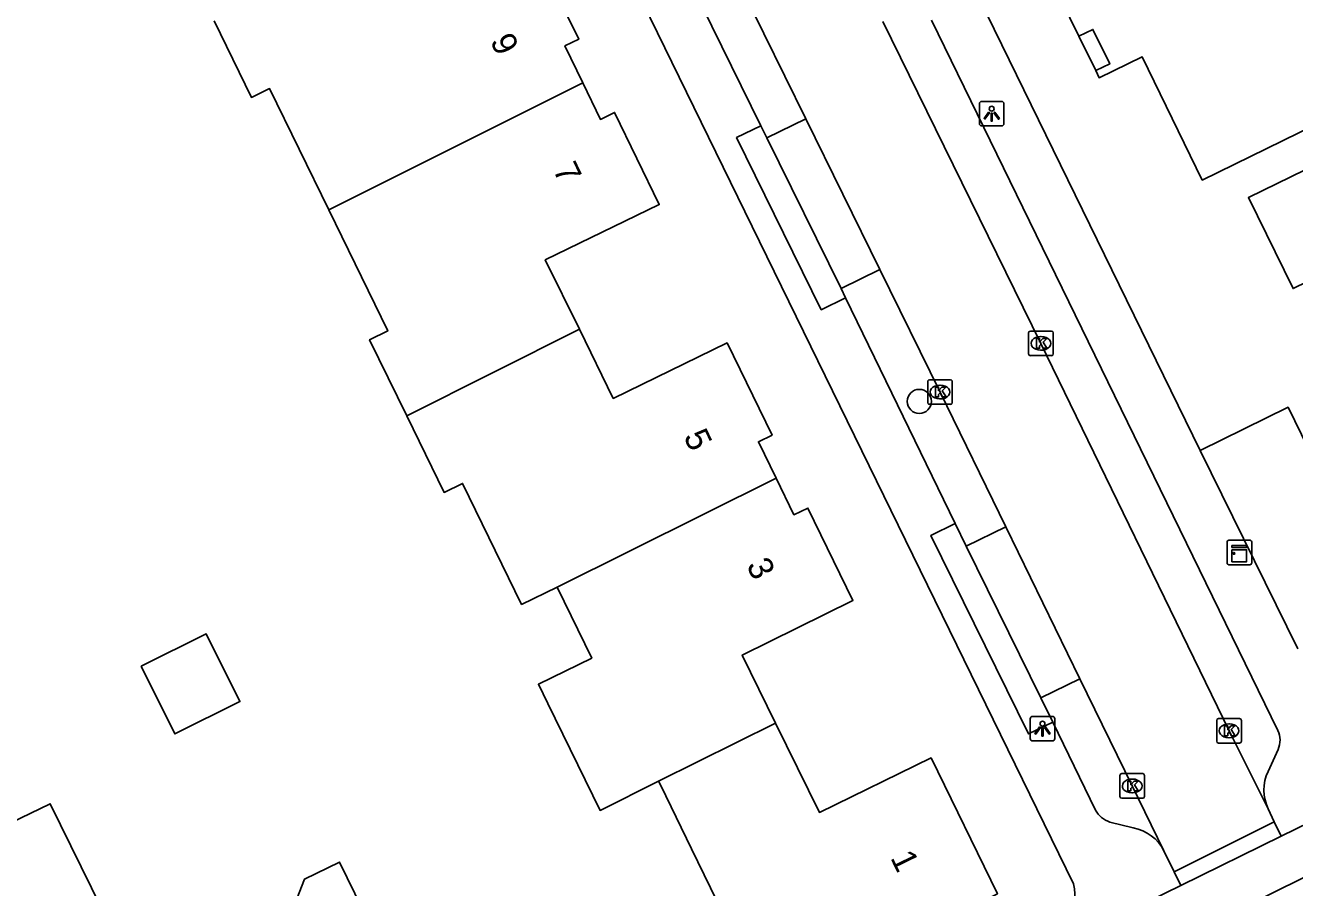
# Model space of a CAD drawing. Extents: x 160457 to 162082, y 388340 to 389736.
# Drawn here: x 160698.8 to 160750.4, y 388835.3 to 388870.3 of the extents above; entities that cross this region are included whole.
import ezdxf

# ---------------------------------------------------------------- set-up
doc = ezdxf.new("R2010")
doc.units = 0
for name, color, linetype in [('IMGEO_Boom', 7, 'Continuous'), ('IMGEO_Fietspad_gesloten', 7, 'Continuous'), ('IMGEO_Kast', 7, 'Continuous'), ('IMGEO_Kolk', 7, 'Continuous'), ('IMGEO_Lichtpunt', 7, 'Continuous'), ('IMGEO_Pand', 7, 'Continuous'), ('IMGEO_Pand_nummerreeks', 7, 'Continuous'), ('IMGEO_Pand_overbouw', 7, 'Continuous'), ('IMGEO_Parkeervlak_open', 7, 'Continuous'), ('IMGEO_Rijbaan_lokaal_gesloten', 7, 'Continuous'), ('IMGEO_Voetpad_open', 7, 'Continuous')]:
    doc.layers.add(name, color=color, linetype=linetype)

msp = doc.modelspace()

# ---------------------------------------------------------------- linework, layer by layer
at = {"layer": 'IMGEO_Boom'}
msp.add_circle((160735.122, 388855.034), 0.489, dxfattribs=at)
at = {"layer": 'IMGEO_Fietspad_gesloten'}
msp.add_lwpolyline([(160688.114, 388804.953), (160696.889, 388809.242), (160739.38, 388830.051), (160752.018, 388836.29), (160804.151, 388861.828), (160812.524, 388865.895)], dxfattribs=at)
at = {"layer": 'IMGEO_Kast'}
for p, q in [((160747.638, 388848.463), (160747.638, 388849.304)), ((160747.638, 388849.304), (160747.638, 388848.463)), ((160747.713, 388849.388), (160748.554, 388849.388)), ((160748.554, 388849.388), (160747.713, 388849.388)), ((160748.638, 388849.313), (160748.638, 388848.472)), ((160748.638, 388848.472), (160748.638, 388849.313)), ((160748.563, 388848.388), (160747.722, 388848.388)), ((160747.722, 388848.388), (160748.563, 388848.388))]:
    msp.add_line(p, q, dxfattribs=at)
for points in [[(160747.833, 388849.178), (160748.433, 388849.178), (160748.433, 388849.093), (160747.833, 388849.093), (160747.833, 388849.178)], [(160747.833, 388849.003), (160748.433, 388849.003), (160748.433, 388848.514), (160747.833, 388848.514), (160747.833, 388849.003)]]:
    msp.add_lwpolyline(points, dxfattribs=at)
msp.add_circle((160747.917, 388848.852), 0.0377, dxfattribs=at)
for centre, start, end in [((160747.716, 388849.31), 92.4484, 184.2845), ((160747.716, 388849.31), 92.4484, 184.2845), ((160748.56, 388849.31), 2.4484, 94.2845), ((160748.56, 388849.31), 2.4484, 94.2845), ((160747.716, 388848.466), 182.4484, 274.2845), ((160747.716, 388848.466), 182.4484, 274.2845), ((160748.56, 388848.466), 272.4484, 4.2845), ((160748.56, 388848.466), 272.4484, 4.2845)]:
    msp.add_arc(centre, 0.0779, start, end, dxfattribs=at)
at = {"layer": 'IMGEO_Kolk'}
for p, q in [((160739.566, 388856.967), (160739.566, 388857.819)), ((160739.641, 388857.893), (160740.493, 388857.893)), ((160740.567, 388857.819), (160740.567, 388856.967)), ((160740.054, 388857.673), (160740.079, 388857.673)), ((160740.493, 388856.893), (160739.641, 388856.893)), ((160740.077, 388857.113), (160740.052, 388857.113)), ((160735.463, 388854.988), (160735.463, 388855.84)), ((160735.538, 388855.914), (160736.39, 388855.914)), ((160736.464, 388855.84), (160736.464, 388854.988)), ((160735.951, 388855.694), (160735.976, 388855.694)), ((160736.39, 388854.914), (160735.538, 388854.914)), ((160735.974, 388855.134), (160735.949, 388855.134)), ((160747.218, 388841.212), (160747.218, 388842.064)), ((160747.293, 388842.138), (160748.145, 388842.138)), ((160747.706, 388841.918), (160747.731, 388841.918)), ((160748.219, 388842.064), (160748.219, 388841.212)), ((160747.729, 388841.358), (160747.704, 388841.358)), ((160748.145, 388841.138), (160747.293, 388841.138)), ((160743.279, 388838.97), (160743.279, 388839.822)), ((160743.354, 388839.896), (160744.206, 388839.896)), ((160744.28, 388839.822), (160744.28, 388838.97)), ((160743.767, 388839.676), (160743.792, 388839.676)), ((160744.206, 388838.896), (160743.354, 388838.896)), ((160743.79, 388839.116), (160743.765, 388839.116))]:
    msp.add_line(p, q, dxfattribs=at)
for points in [[(160739.566, 388856.967), (160739.566, 388857.819)], [(160739.641, 388857.893), (160740.493, 388857.893)], [(160740.567, 388857.819), (160740.567, 388856.967)], [(160739.887, 388857.593), (160740.01, 388857.593), (160740.01, 388857.442), (160740.14, 388857.593), (160740.304, 388857.593), (160740.158, 388857.442), (160740.311, 388857.193), (160740.159, 388857.193), (160740.074, 388857.357), (160740.01, 388857.29), (160740.01, 388857.193), (160739.887, 388857.193), (160739.887, 388857.593)], [(160740.493, 388856.893), (160739.641, 388856.893)], [(160735.463, 388854.988), (160735.463, 388855.84)], [(160735.538, 388855.914), (160736.39, 388855.914)], [(160736.464, 388855.84), (160736.464, 388854.988)], [(160735.784, 388855.614), (160735.907, 388855.614), (160735.907, 388855.463), (160736.037, 388855.614), (160736.201, 388855.614), (160736.055, 388855.463), (160736.208, 388855.214), (160736.056, 388855.214), (160735.971, 388855.378), (160735.907, 388855.311), (160735.907, 388855.214), (160735.784, 388855.214), (160735.784, 388855.614)], [(160736.39, 388854.914), (160735.538, 388854.914)], [(160747.218, 388841.212), (160747.218, 388842.064)], [(160747.293, 388842.138), (160748.145, 388842.138)], [(160747.539, 388841.838), (160747.662, 388841.838), (160747.662, 388841.687), (160747.792, 388841.838), (160747.956, 388841.838), (160747.81, 388841.687), (160747.963, 388841.438), (160747.811, 388841.438), (160747.726, 388841.602), (160747.662, 388841.535), (160747.662, 388841.438), (160747.539, 388841.438), (160747.539, 388841.838)], [(160748.219, 388842.064), (160748.219, 388841.212)], [(160748.145, 388841.138), (160747.293, 388841.138)], [(160743.279, 388838.97), (160743.279, 388839.822)], [(160743.354, 388839.896), (160744.206, 388839.896)], [(160744.28, 388839.822), (160744.28, 388838.97)], [(160743.6, 388839.596), (160743.723, 388839.596), (160743.723, 388839.445), (160743.853, 388839.596), (160744.017, 388839.596), (160743.871, 388839.445), (160744.024, 388839.196), (160743.872, 388839.196), (160743.787, 388839.36), (160743.723, 388839.293), (160743.723, 388839.196), (160743.6, 388839.196), (160743.6, 388839.596)], [(160744.206, 388838.896), (160743.354, 388838.896)]]:
    msp.add_lwpolyline(points, dxfattribs=at)
for centre, start, end in [((160739.643, 388857.817), 91.552, 178.448), ((160739.643, 388857.817), 91.552, 178.448), ((160740.491, 388857.817), 1.552, 88.448), ((160740.491, 388857.817), 1.552, 88.448), ((160739.643, 388856.969), 181.552, 268.448), ((160739.643, 388856.969), 181.552, 268.448), ((160740.491, 388856.969), 271.552, 358.448), ((160740.491, 388856.969), 271.552, 358.448), ((160735.54, 388855.838), 91.552, 178.448), ((160735.54, 388855.838), 91.552, 178.448), ((160736.388, 388855.838), 1.552, 88.448), ((160736.388, 388855.838), 1.552, 88.448), ((160735.54, 388854.99), 181.552, 268.448), ((160735.54, 388854.99), 181.552, 268.448), ((160736.388, 388854.99), 271.552, 358.448), ((160736.388, 388854.99), 271.552, 358.448), ((160747.295, 388842.062), 91.552, 178.448), ((160747.295, 388842.062), 91.552, 178.448), ((160748.143, 388842.062), 1.552, 88.448), ((160748.143, 388842.062), 1.552, 88.448), ((160747.295, 388841.214), 181.552, 268.448), ((160747.295, 388841.214), 181.552, 268.448), ((160748.143, 388841.214), 271.552, 358.448), ((160748.143, 388841.214), 271.552, 358.448), ((160743.356, 388839.82), 91.552, 178.448), ((160743.356, 388839.82), 91.552, 178.448), ((160744.204, 388839.82), 1.552, 88.448), ((160744.204, 388839.82), 1.552, 88.448), ((160743.356, 388838.972), 181.552, 268.448), ((160743.356, 388838.972), 181.552, 268.448), ((160744.204, 388838.972), 271.552, 358.448), ((160744.204, 388838.972), 271.552, 358.448)]:
    msp.add_arc(centre, 0.0765, start, end, dxfattribs=at)
for centre, major_axis, ratio, start_param, end_param in [((160740.053, 388857.393), (-0.387, 0.002), 0.722429, 4.712389, 7.853982), ((160740.078, 388857.393), (-0.39, 0.002), 0.717154, 1.570796, 4.712389), ((160735.95, 388855.414), (-0.387, 0.002), 0.722429, 4.712389, 7.853982), ((160735.975, 388855.414), (-0.39, 0.002), 0.717154, 1.570796, 4.712389), ((160747.705, 388841.638), (-0.387, 0.002), 0.722429, 4.712389, 7.853982), ((160747.73, 388841.638), (-0.39, 0.002), 0.717154, 1.570796, 4.712389), ((160743.766, 388839.396), (-0.387, 0.002), 0.722429, 4.712389, 7.853982), ((160743.791, 388839.396), (-0.39, 0.002), 0.717154, 1.570796, 4.712389)]:
    msp.add_ellipse(centre, major_axis=major_axis, ratio=ratio, start_param=start_param, end_param=end_param, dxfattribs=at)
at = {"layer": 'IMGEO_Lichtpunt'}
for p, q in [((160737.566, 388867.136), (160737.566, 388866.329)), ((160737.566, 388867.136), (160737.566, 388866.329)), ((160738.468, 388867.231), (160737.66, 388867.231)), ((160738.468, 388867.231), (160737.66, 388867.231)), ((160738.562, 388866.329), (160738.562, 388867.136)), ((160738.562, 388866.329), (160738.562, 388867.136)), ((160737.66, 388866.235), (160738.468, 388866.235)), ((160737.66, 388866.235), (160738.468, 388866.235)), ((160739.632, 388842.131), (160739.632, 388841.324)), ((160739.632, 388842.131), (160739.632, 388841.324)), ((160740.534, 388842.226), (160739.726, 388842.226)), ((160740.534, 388842.226), (160739.726, 388842.226)), ((160740.628, 388841.324), (160740.628, 388842.131)), ((160740.628, 388841.324), (160740.628, 388842.131)), ((160739.726, 388841.23), (160740.534, 388841.23)), ((160739.726, 388841.23), (160740.534, 388841.23))]:
    msp.add_line(p, q, dxfattribs=at)
for points in [[(160737.94, 388866.8), (160737.979, 388866.772), (160737.791, 388866.51), (160737.753, 388866.537), (160737.94, 388866.8)], [(160738.042, 388866.752), (160738.089, 388866.752), (160738.089, 388866.43), (160738.042, 388866.43), (160738.042, 388866.752)], [(160738.152, 388866.772), (160738.19, 388866.799), (160738.377, 388866.537), (160738.338, 388866.509), (160738.152, 388866.772)], [(160740.006, 388841.795), (160740.045, 388841.767), (160739.857, 388841.505), (160739.819, 388841.532), (160740.006, 388841.795)], [(160740.108, 388841.747), (160740.155, 388841.747), (160740.155, 388841.425), (160740.108, 388841.425), (160740.108, 388841.747)], [(160740.218, 388841.767), (160740.256, 388841.794), (160740.443, 388841.532), (160740.404, 388841.504), (160740.218, 388841.767)]]:
    msp.add_lwpolyline(points, dxfattribs=at)
for centre in [(160738.065, 388866.934), (160740.131, 388841.929)]:
    msp.add_circle(centre, 0.0994, dxfattribs=at)
for centre, start, end in [((160737.66, 388867.136), 90, 180), ((160737.66, 388867.136), 90, 180), ((160738.468, 388867.136), 0, 90), ((160738.468, 388867.136), 0, 90), ((160737.66, 388866.329), 180, 270), ((160737.66, 388866.329), 180, 270), ((160738.468, 388866.329), 270, 0), ((160738.468, 388866.329), 270, 360), ((160739.726, 388842.131), 90, 180), ((160739.726, 388842.131), 90, 180), ((160740.534, 388842.131), 0, 90), ((160740.534, 388842.131), 0, 90), ((160739.726, 388841.324), 180, 270), ((160739.726, 388841.324), 180, 270), ((160740.534, 388841.324), 270, 0), ((160740.534, 388841.324), 270, 360)]:
    msp.add_arc(centre, 0.0946, start, end, dxfattribs=at)
at = {"layer": 'IMGEO_Pand'}
for points in [[(160743.031, 388878.682), (160744.402, 388875.881), (160739.785, 388873.622), (160741.614, 388869.885), (160742.18, 388870.162), (160742.864, 388868.756), (160742.295, 388868.485), (160742.434, 388868.193), (160744.178, 388869.046), (160746.63, 388864.032), (160755.794, 388868.515), (160753.342, 388873.528), (160751.802, 388876.678), (160752.565, 388877.051), (160750.081, 388882.13)], [(160713.447, 388874.052), (160714.817, 388871.237), (160719.445, 388873.496), (160721.27, 388869.757), (160720.713, 388869.485), (160721.437, 388867.984)], [(160711.105, 388862.816), (160708.698, 388867.75), (160707.963, 388867.392), (160706.442, 388870.511)], [(160711.105, 388862.816), (160721.437, 388867.984)], [(160721.437, 388867.984), (160722.153, 388866.501), (160722.732, 388866.781), (160724.548, 388863.034), (160719.913, 388860.788), (160721.297, 388857.969)], [(160750.812, 388864.45), (160748.507, 388863.323), (160750.319, 388859.62), (160752.624, 388860.747)], [(160714.281, 388854.442), (160712.77, 388857.539), (160713.504, 388857.897), (160711.105, 388862.816)], [(160721.297, 388857.969), (160714.281, 388854.442)], [(160721.297, 388857.969), (160722.678, 388855.155), (160727.307, 388857.413), (160729.136, 388853.664), (160728.578, 388853.393), (160729.299, 388851.912)], [(160755.566, 388854.723), (160751.768, 388851.437), (160750.115, 388854.798), (160746.543, 388853.042)], [(160720.392, 388847.485), (160718.95, 388846.781), (160716.551, 388851.699), (160715.798, 388851.332), (160714.281, 388854.442)], [(160750.513, 388844.965), (160746.543, 388853.042)], [(160720.392, 388847.485), (160729.299, 388851.912)], [(160729.299, 388851.912), (160730.023, 388850.423), (160730.593, 388850.692), (160732.422, 388846.942), (160727.922, 388844.718), (160729.279, 388841.953)], [(160724.522, 388839.587), (160722.139, 388838.402), (160720.022, 388842.743), (160719.636, 388843.534), (160721.803, 388844.592), (160720.392, 388847.485)], [(160703.475, 388844.266), (160706.119, 388845.585), (160707.494, 388842.828), (160704.85, 388841.509), (160703.475, 388844.266)], [(160729.279, 388841.953), (160731.062, 388838.319), (160735.599, 388840.535), (160738.298, 388835.011), (160728.968, 388830.464), (160725.86, 388836.841), (160724.605, 388839.416), (160724.522, 388839.587)], [(160724.522, 388839.587), (160729.279, 388841.953)], [(160698.184, 388837.89), (160699.781, 388838.674), (160702.304, 388833.55), (160702.906, 388833.846), (160704.819, 388829.96), (160701.206, 388828.193)], [(160710.403, 388832.586), (160709.591, 388834.255), (160710.125, 388835.607), (160711.547, 388836.298), (160712.789, 388833.746)]]:
    msp.add_lwpolyline(points, dxfattribs=at)
at = {"layer": 'IMGEO_Pand_overbouw'}
msp.add_lwpolyline([(160742.295, 388868.485), (160742.864, 388868.756), (160742.18, 388870.162), (160741.614, 388869.885)], close=True, dxfattribs=at)
at = {"layer": 'IMGEO_Parkeervlak_open'}
for points in [[(160728.92, 388865.748), (160730.503, 388866.526)], [(160733.518, 388860.392), (160731.941, 388859.617)], [(160737.034, 388849.147), (160738.64, 388849.931)], [(160741.656, 388843.751), (160740.069, 388842.977)]]:
    msp.add_lwpolyline(points, dxfattribs=at)
at = {"layer": 'IMGEO_Rijbaan_lokaal_gesloten'}
for points in [[(160730.503, 388866.526), (160727.942, 388871.738), (160725.648, 388876.442)], [(160733.637, 388870.475), (160740.066, 388857.393), (160747.718, 388841.637), (160749.315, 388838.459)], [(160730.503, 388866.526), (160733.518, 388860.392)], [(160738.64, 388849.931), (160735.965, 388855.414), (160733.518, 388860.392)], [(160738.64, 388849.931), (160741.656, 388843.751)], [(160741.656, 388843.751), (160743.781, 388839.396), (160745.065, 388836.754)], [(160749.558, 388837.942), (160749.315, 388838.459)], [(160745.48, 388835.906), (160749.558, 388837.942)], [(160745.065, 388836.754), (160745.48, 388835.906)]]:
    msp.add_lwpolyline(points, dxfattribs=at)
at = {"layer": 'IMGEO_Voetpad_open'}
for points in [[(160746.543, 388853.042), (160702.295, 388943.534)], [(160741.386, 388835.41), (160711.402, 388896.761), (160699.17, 388921.78)], [(160724.301, 388875.158), (160728.675, 388866.245)], [(160749.695, 388841.654), (160735.611, 388870.54)], [(160728.675, 388866.245), (160727.688, 388865.759), (160731.135, 388858.763), (160732.122, 388859.249)], [(160728.675, 388866.245), (160728.92, 388865.748)], [(160731.941, 388859.617), (160728.92, 388865.748)], [(160731.941, 388859.617), (160732.122, 388859.249)], [(160732.122, 388859.249), (160736.583, 388850.065)], [(160736.583, 388850.065), (160735.596, 388849.58), (160739.565, 388841.509), (160740.552, 388841.994)], [(160736.583, 388850.065), (160737.034, 388849.147)], [(160740.069, 388842.977), (160737.034, 388849.147)], [(160740.069, 388842.977), (160740.552, 388841.994)], [(160740.552, 388841.994), (160742.283, 388838.406)], [(160749.303, 388839.989), (160749.711, 388840.883)], [(160755.282, 388840.029), (160755.104, 388839.929), (160749.832, 388837.359)], [(160742.873, 388837.927), (160743.819, 388837.69)], [(160749.558, 388837.942), (160749.832, 388837.359)], [(160749.832, 388837.359), (160745.755, 388835.344)], [(160745.755, 388835.344), (160745.48, 388835.906)], [(160745.755, 388835.344), (160740.243, 388832.65)]]:
    msp.add_lwpolyline(points, dxfattribs=at)
for centre, radius, start, end in [((160748.903, 388841.252), 0.889, 335.473, 26.9047), ((160750.904, 388839.237), 1.769, 154.8218, 206.0769), ((160743.257, 388839.003), 1.142, 211.4997, 250.3564), ((160743.52, 388835.994), 1.722, 26.1791, 79.9929), ((160738.931, 388834.81), 2.527, 301.27, 13.7381)]:
    msp.add_arc(centre, radius, start, end, dxfattribs=at)

# ---------------------------------------------------------------- texts
at = {"layer": 'IMGEO_Pand_nummerreeks'}
for s, rotation, p in [('9', 296.0015, (160717.652, 388869.69)), ('7', 296.0015, (160720.204, 388864.459)), ('5', 296.0351, (160725.518, 388853.603)), ('3', 296.035, (160728.075, 388848.368)), ('1', 296.0407, (160733.93, 388836.478))]:
    msp.add_text(s, height=1, rotation=rotation, dxfattribs=at).set_placement(p)

doc.saveas('drawing.dxf')
